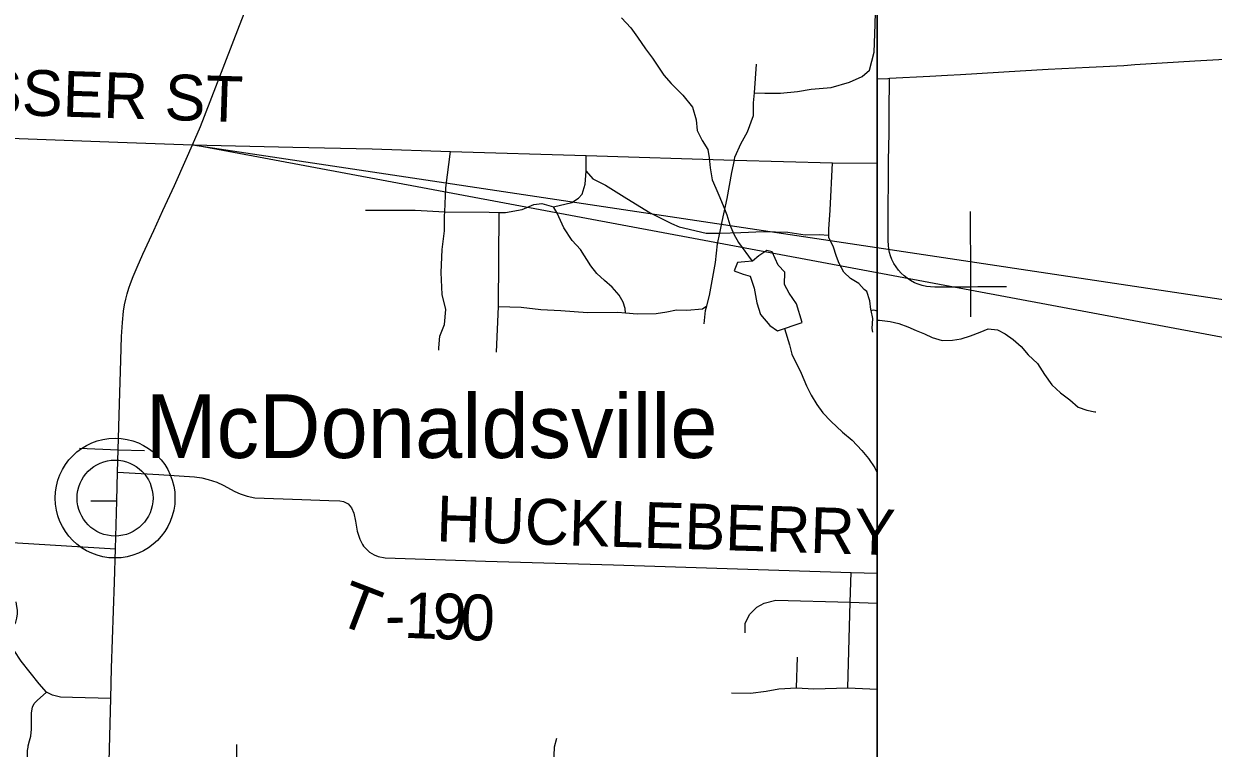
# Model space of a CAD drawing. Extents: x 25.6 to 80.6, y 0.2 to 24.5.
# Drawn here: x 38.894 to 41.848, y 17.932 to 19.73 of the extents above; entities that cross this region are included whole.
import ezdxf

# ---------------------------------------------------------------- set-up
doc = ezdxf.new("R2010")
doc.units = 0
for name, color, linetype in [('GM_X_County_Road', 7, 'Continuous'), ('GM_X_County_Road_Text', 7, 'Continuous'), ('GM_X_Minor_Lake', 7, 'Continuous'), ('GM_X_Minor_River', 7, 'Continuous'), ('GM_X_State_Route', 7, 'Continuous'), ('GM_X_Township_Road', 7, 'Continuous'), ('GM_X_Township_Road_Text', 7, 'Continuous'), ('GM_X_Unincorporated', 7, 'Continuous'), ('GM_X_Unincorporated_Location', 7, 'Continuous'), ('GM_X_Unincorporated_Text', 7, 'Continuous'), ('SH_Data', 7, 'Continuous'), ('SH_Text', 7, 'Continuous')]:
    doc.layers.add(name, color=color, linetype=linetype)

msp = doc.modelspace()

# ---------------------------------------------------------------- linework, layer by layer
at = {"layer": 'GM_X_County_Road'}
for points in [[(41.0437, 19.5951), (41.144, 19.6006), (41.1874, 19.603), (41.2197, 19.6047), (41.3686, 19.6136), (41.4381, 19.6175), (41.5399, 19.623), (41.6256, 19.6272), (41.6528, 19.6291), (41.8018, 19.6381), (41.9656, 19.6477), (42.0127, 19.6503), (42.0586, 19.653), (42.1716, 19.6592), (42.2212, 19.6621), (42.2907, 19.6661), (42.3428, 19.6688), (42.443, 19.6746), (42.459, 19.6756)], [(41.0128, 19.5934), (41.0397, 19.5949), (41.0437, 19.5951)], [(37.6128, 19.4872), (38.0081, 19.473), (38.1648, 19.4698), (38.614, 19.4559), (39.1271, 19.4367), (39.3128, 19.4303)], [(39.3128, 19.4303), (39.5614, 19.4242), (39.7592, 19.4197), (39.9534, 19.4131), (40.2901, 19.4035), (40.6584, 19.392), (40.902, 19.3855), (41.0128, 19.3842)]]:
    msp.add_lwpolyline(points, dxfattribs=at)
at = {"layer": 'GM_X_Minor_Lake'}
for points in [[(40.8269, 18.9891), (40.8127, 19.0352), (40.7949, 19.0616), (40.7833, 19.0827), (40.7837, 19.1139), (40.7668, 19.1311), (40.7527, 19.1644), (40.7391, 19.1673), (40.7195, 19.1541), (40.7037, 19.141), (40.6848, 19.1393), (40.6659, 19.1376), (40.6578, 19.117), (40.6799, 19.1089), (40.6974, 19.1037), (40.7076, 19.0743), (40.7141, 19.0379), (40.7235, 19.0084), (40.7466, 18.9813), (40.7657, 18.9679)], [(40.7657, 18.9679), (40.8269, 18.9891)]]:
    msp.add_lwpolyline(points, dxfattribs=at)
at = {"layer": 'GM_X_Minor_River'}
for points in [[(40.3779, 19.7455), (40.401, 19.7207), (40.418, 19.6973), (40.438, 19.668), (40.455, 19.6454), (40.4697, 19.6228), (40.4835, 19.6032), (40.5012, 19.5821), (40.5304, 19.5529), (40.5543, 19.5235), (40.5638, 19.4917), (40.5664, 19.4652), (40.5788, 19.4403), (40.5927, 19.4184), (40.596, 19.398), (40.5986, 19.3729), (40.6035, 19.3434), (40.6128, 19.3222), (40.6222, 19.2995), (40.6324, 19.2754), (40.6394, 19.2557), (40.6473, 19.2315), (40.6574, 19.2081), (40.6683, 19.1877), (40.703, 19.141)], [(40.783, 18.9738), (40.795, 18.9333), (40.8013, 18.9098), (40.8246, 18.863), (40.8372, 18.8313), (40.8488, 18.8079), (40.8635, 18.7852), (40.8782, 18.7642), (40.8981, 18.7439), (40.9273, 18.7161), (40.951, 18.6967), (40.9748, 18.6711), (40.9918, 18.6508), (41.0072, 18.6275), (41.0128, 18.6154)], [(41.0128, 18.9948), (41.0189, 18.9943), (41.0455, 18.9908), (41.0667, 18.9865), (41.0896, 18.9777), (41.1101, 18.9688), (41.1307, 18.9607), (41.1497, 18.9511), (41.1748, 18.9438), (41.2006, 18.9449), (41.2217, 18.9482), (41.2451, 18.9553), (41.2685, 18.9647), (41.2889, 18.9726), (41.3116, 18.9706), (41.3307, 18.9602), (41.3505, 18.9467), (41.3704, 18.9295), (41.3881, 18.9085), (41.4111, 18.8867), (41.4288, 18.8596), (41.4465, 18.834), (41.4688, 18.8138), (41.4917, 18.7966), (41.5124, 18.7786), (41.5337, 18.7713), (41.5534, 18.7669), (41.5564, 18.767)]]:
    msp.add_lwpolyline(points, dxfattribs=at)
at = {"layer": 'GM_X_State_Route'}
msp.add_lwpolyline([(39.1045, 17.8675), (39.1098, 18.0552), (39.1118, 18.1304), (39.1165, 18.2731), (39.1191, 18.3436), (39.1211, 18.4267), (39.1245, 18.5455), (39.1252, 18.5815), (39.1264, 18.6174), (39.1278, 18.6724), (39.1316, 18.7867), (39.135, 18.8954), (39.1366, 18.954), (39.1385, 18.9891), (39.1413, 19.0169), (39.1436, 19.0327), (39.1468, 19.0468), (39.1501, 19.0597), (39.1542, 19.0736), (39.1583, 19.0857), (39.1651, 19.1029), (39.1749, 19.126), (39.1893, 19.1583), (39.2164, 19.2174), (39.2393, 19.2671), (39.2675, 19.3286), (39.297, 19.394), (39.3128, 19.4303), (39.3322, 19.4758), (39.3566, 19.5376), (39.4294, 19.7265), (39.4558, 19.7951)], dxfattribs=at)
at = {"layer": 'GM_X_Township_Road'}
for p, q in [((40.2903, 19.3647), (40.2901, 19.4035)), ((41.2455, 19.003), (41.2461, 19.0768)), ((39.0605, 18.5462), (39.1245, 18.5455)), ((40.8125, 18.0818), (40.8149, 18.1573))]:
    msp.add_line(p, q, dxfattribs=at)
for points in [[(40.7082, 19.5587), (40.7342, 19.5583), (40.7726, 19.5582), (40.8152, 19.5625), (40.8493, 19.5682), (40.899, 19.5724), (40.9445, 19.5852), (40.9757, 19.5994), (40.9942, 19.615), (41.0056, 19.6604), (41.0085, 19.7286), (41.0099, 19.7897), (41.0085, 19.8409), (41.0128, 19.8866)], [(40.5834, 18.9855), (40.5864, 19.0184), (40.5898, 19.0303), (40.5969, 19.0558), (40.6119, 19.1381), (40.6164, 19.1844), (40.622, 19.2104), (40.6284, 19.2397), (40.6403, 19.2965), (40.6524, 19.3608), (40.6584, 19.392), (40.6598, 19.3997), (40.6606, 19.4013), (40.6748, 19.4326), (40.6913, 19.4625), (40.7062, 19.5028), (40.7062, 19.5342), (40.7082, 19.5587), (40.7138, 19.6299)], [(41.0407, 19.2786), (41.0409, 19.3366), (41.0413, 19.3913), (41.0426, 19.4585), (41.0427, 19.4908), (41.043, 19.5294), (41.0435, 19.5779), (41.0437, 19.5951)], [(39.9244, 18.9203), (39.9244, 18.9261), (39.9273, 18.9549), (39.9388, 18.9836), (39.9417, 19.021), (39.9331, 19.0583), (39.9302, 19.113), (39.9331, 19.1704), (39.9389, 19.2164), (39.9389, 19.2538), (39.9393, 19.2632), (39.9418, 19.3228), (39.9534, 19.4131)], [(41.002, 18.9645), (41.0006, 18.9734), (41.002, 18.9988), (40.998, 19.0189), (40.9976, 19.0213), (40.9946, 19.0422), (40.9871, 19.0661), (40.9812, 19.0706), (40.9677, 19.0856), (40.9468, 19.0976), (40.9303, 19.114), (40.9184, 19.1349), (40.9124, 19.1529), (40.9034, 19.1783), (40.893, 19.1992), (40.893, 19.2058), (40.893, 19.2202), (40.896, 19.268), (40.902, 19.3855)], [(40.2088, 19.2757), (40.2545, 19.2864), (40.2709, 19.2975), (40.2801, 19.3078), (40.2882, 19.3326), (40.2903, 19.3647)], [(40.2903, 19.3647), (40.3069, 19.3456), (40.3385, 19.3298), (40.3916, 19.2967), (40.4491, 19.2608), (40.5023, 19.2349), (40.521, 19.2262), (40.5885, 19.2104), (40.622, 19.2104), (40.6747, 19.2118), (40.7308, 19.2147), (40.7911, 19.2132), (40.8342, 19.206), (40.8687, 19.2074), (40.893, 19.2058)], [(39.742, 19.2675), (39.8656, 19.2675), (39.9393, 19.2632), (40.0496, 19.2631), (40.074, 19.2622), (40.0898, 19.2616), (40.1317, 19.2692), (40.1604, 19.2821), (40.1804, 19.2839), (40.2088, 19.2757)], [(40.0676, 18.9154), (40.0725, 19.0281), (40.074, 19.2622)], [(40.3884, 19.0125), (40.3872, 19.0236), (40.3822, 19.0395), (40.3721, 19.0567), (40.3549, 19.0761), (40.3362, 19.0927), (40.3168, 19.1106), (40.3018, 19.1293), (40.2759, 19.1696), (40.2558, 19.1926), (40.235, 19.2235), (40.2185, 19.2602), (40.2088, 19.2757)], [(41.2461, 19.0768), (41.2238, 19.0765), (41.1815, 19.0765), (41.1566, 19.0765), (41.1454, 19.0771), (41.1355, 19.0783), (41.1246, 19.0807), (41.1151, 19.0837), (41.106, 19.0875), (41.0961, 19.0929), (41.0879, 19.0985), (41.0801, 19.1046), (41.0728, 19.1114), (41.0661, 19.1188), (41.0601, 19.1267), (41.0549, 19.1352), (41.0499, 19.1452), (41.0462, 19.1545), (41.0437, 19.1628), (41.042, 19.1713), (41.041, 19.1799), (41.0404, 19.1924), (41.0406, 19.216), (41.0407, 19.2786)], [(41.2461, 19.0768), (41.246, 19.1063), (41.2446, 19.2569), (41.2447, 19.2644)], [(41.3347, 19.0773), (41.3158, 19.0772), (41.2635, 19.077), (41.2461, 19.0768)], [(40.0725, 19.0281), (40.1293, 19.0266), (40.1781, 19.0208), (40.2277, 19.0187), (40.2938, 19.0136), (40.3686, 19.0143), (40.3884, 19.0125), (40.4167, 19.01), (40.4641, 19.0114), (40.4907, 19.015), (40.5144, 19.02), (40.5403, 19.0193), (40.5791, 19.0228), (40.5898, 19.0303)], [(40.998, 19.0189), (41.0037, 19.0205), (41.0128, 19.0179)], [(39.0316, 18.6764), (39.1278, 18.6724), (39.1933, 18.671)], [(39.1264, 18.6174), (39.2291, 18.6111), (39.3178, 18.6055), (39.3356, 18.6028), (39.3517, 18.5992), (39.3727, 18.592), (39.3889, 18.5851), (39.4175, 18.569), (39.4309, 18.5631), (39.4484, 18.5571), (39.4671, 18.5535), (39.5838, 18.5492), (39.6512, 18.5469), (39.6782, 18.546), (39.6874, 18.5446), (39.6993, 18.5381), (39.7071, 18.5285), (39.7134, 18.515), (39.7177, 18.495), (39.7219, 18.4707), (39.7282, 18.4506), (39.7346, 18.4378), (39.7374, 18.4332), (39.7519, 18.418), (39.7634, 18.4115), (39.7736, 18.4075), (39.791, 18.4042), (40.0405, 18.3963), (40.3583, 18.3868), (40.9485, 18.3675), (41.0128, 18.3664)], [(38.0872, 18.4715), (38.1137, 18.4699), (38.3845, 18.4588), (38.5779, 18.4524), (38.6581, 18.4508), (38.8779, 18.4416), (39.1211, 18.4267)], [(40.9399, 18.0818), (40.946, 18.2945), (40.9485, 18.3675)], [(39.1098, 18.0552), (39.0148, 18.0575), (38.9845, 18.0586), (38.9645, 18.0634), (38.9504, 18.071), (38.932, 18.0916), (38.8872, 18.1478), (38.8696, 18.174), (38.8631, 18.1892), (38.8603, 18.2), (38.8603, 18.2092), (38.8625, 18.2206), (38.869, 18.2363), (38.8739, 18.2444), (38.8766, 18.2547), (38.8782, 18.265), (38.8777, 18.2742), (38.8766, 18.2834), (38.8744, 18.2954)], [(40.6851, 18.2179), (40.6851, 18.2414), (40.6962, 18.2636), (40.7141, 18.282), (40.7321, 18.2921), (40.7618, 18.2995), (40.946, 18.2945), (41.0128, 18.292)], [(40.6517, 18.0694), (40.6987, 18.0682), (40.737, 18.0731), (40.7692, 18.0793), (40.8125, 18.0818), (40.8558, 18.0793), (40.9399, 18.0818), (41.0128, 18.0784)], [(38.9, 17.7303), (38.9007, 17.7529), (38.903, 17.9262), (38.9034, 17.9298), (38.9041, 17.9344), (38.9048, 17.9374), (38.9076, 17.9498), (38.9114, 17.9611), (38.9125, 17.979), (38.9125, 18.0196), (38.9152, 18.0337), (38.919, 18.0423), (38.9271, 18.0504), (38.9504, 18.071)], [(39.4216, 17.7303), (39.4217, 17.7671), (39.4229, 17.858), (39.4229, 17.9408)], [(40.2038, 17.7303), (40.2042, 17.7392), (40.2116, 17.9347), (40.2177, 17.9568)]]:
    msp.add_lwpolyline(points, dxfattribs=at)
at = {"layer": 'GM_X_Unincorporated'}
for radius in [0.1488, 0.0943]:
    msp.add_circle((39.1203, 18.5527), radius, dxfattribs=at)
at = {"layer": 'GM_X_Unincorporated_Location'}
msp.add_line((39.1203, 18.5527), (39.1203, 18.5527), dxfattribs=at)
at = {"layer": 'SH_Data'}
msp.add_line((41.0128, 21.1303), (41.0128, 14.3303), dxfattribs=at)
at = {"layer": 'SH_Text'}
for points in [[(37.6128, 17.7303), (41.0128, 17.7303), (41.0128, 21.1303), (37.6128, 21.1303)], [(37.6128, 17.7303), (41.0128, 17.7303), (41.0128, 21.1303), (37.6128, 21.1303)], [(41.0128, 17.7303), (44.4128, 17.7303), (44.4128, 21.1303), (41.0128, 21.1303)], [(41.0128, 17.7303), (44.4128, 17.7303), (44.4128, 21.1303), (41.0128, 21.1303)], [(44.7372, 18.6163), (44.7372, 18.4163), (39.3128, 19.4303)]]:
    msp.add_lwpolyline(points, close=True, dxfattribs=at)

# ---------------------------------------------------------------- texts
at = {"layer": 'GM_X_County_Road_Text'}
msp.add_text('STRAUSSER ST', height=0.113636, rotation=358.1798, dxfattribs=at).set_placement((38.2715, 19.5229))
at = {"layer": 'GM_X_Township_Road_Text'}
for s, height, rotation, p in [('HUCKLEBERRY', 0.113636, 358.2362, (39.9171, 18.4454)), ('T', 0.1136, 338.9093, (39.6648, 18.2435)), ('1', 0.1136, 357.8034, (39.8366, 18.2059)), ('9', 0.1136, 358.0891, (39.9072, 18.2032)), ('0', 0.1136, 358.1737, (39.9773, 18.2008)), ('-', 0.1136, 1.465, (39.7919, 18.2047))]:
    msp.add_text(s, height=height, rotation=rotation, dxfattribs=at).set_placement(p)
at = {"layer": 'GM_X_Unincorporated_Text'}
msp.add_text('McDonaldsville', height=0.157955, rotation=0, dxfattribs=at).set_placement((39.1964, 18.6522))

doc.saveas('drawing.dxf')
